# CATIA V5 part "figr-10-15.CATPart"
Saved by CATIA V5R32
Part number: Part1
Bounding box of the stored display mesh (mm): x -59.023 to 59.085, y -59.069 to 29.542, z 0 to 150
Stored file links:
  D:\PROJECTS\Project 2022\CATIA V5 6R 2022\Resources\Part Files\c10_catia_v5_6r2022_prt\c10_catia_v5_6r2022_prt\figr-10-15.CATPart
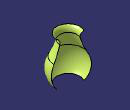
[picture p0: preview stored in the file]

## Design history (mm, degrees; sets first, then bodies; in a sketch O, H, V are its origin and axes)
Set1
  Sketch1 on yz-plane, origin (0, 0, 0), H (0, 1, 0), V (0, 0, 1)
    arc A1 centre (219.5293, 176.8574) radius 194.8379 from (50.3627, 80.1907) to (30.3627, 130.1907) cw
    arc A2 centre (-7.8186, 46.9443) radius 67.0103 from (50.3627, 80.1907) to (40, 0) cw
    arc A3 centre (47.0688, 134.312) radius 17.207 from (30.3627, 130.1907) to (40, 150) cw
    axis line L1 (0, 156.5671) -> (0, -24.1442)
    vertical: L1 V
  Revol1: Element1 Sketch1, Angle1 -60
Body1 (main body)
